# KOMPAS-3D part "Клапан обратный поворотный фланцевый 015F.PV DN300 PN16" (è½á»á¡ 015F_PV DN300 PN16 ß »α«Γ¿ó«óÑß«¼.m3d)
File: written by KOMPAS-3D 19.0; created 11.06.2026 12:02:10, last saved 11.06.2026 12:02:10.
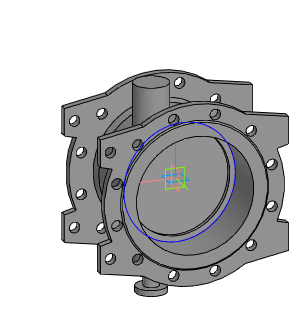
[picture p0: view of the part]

Document properties: Автор: Энергия; Полное имя файла: Z:\3.Личные\kachalov\001_3d для проектировщиков\5.5 Тип 015F.PV Клапан обратный поворотный с двумя эксцентриками\_stp_Клапан 015F.PV DN300-DN1200 с противовесом\Клапан 015F_PV DN300 PN16 с противовесом.m3d

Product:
- Part/product: Клапан обратный поворотный фланцевый 015F.PV DN300 PN16

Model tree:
1. Операция без истории:1
2. Сплайн:1
     Координата Y = 30; Координата Z = 150; Вес = 1; Координата X = 300; Координата Y = 69.4957; Координата Z = 150; Вес = 0.333333; Координата X = 300; Координата Y = 69.4957; Координата Z = -150; Вес = 0.333333; Координата Y = 30; Координата Z = -150; Вес = 1; Координата X = -300; Координата Y = -9.49575; Координата Z = -150; Вес = 0.333333; Координата X = -300; Координата Y = -9.49575; Координата Z = 150; Вес = 0.333333; Порядок = 4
